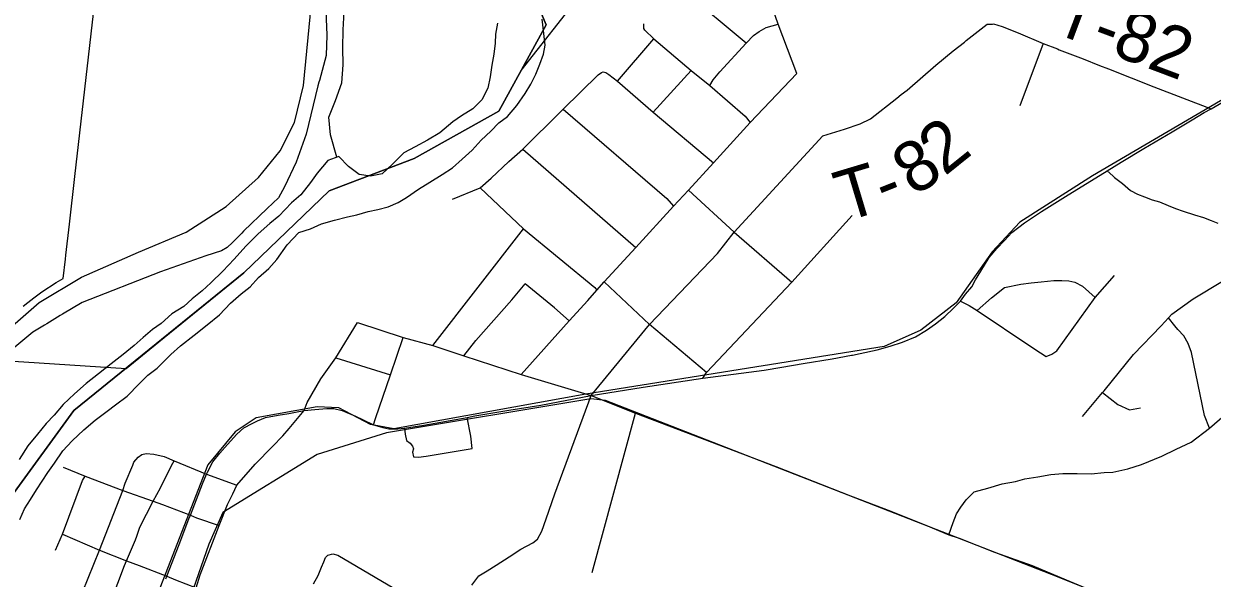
# Model space of a CAD drawing. Extents: x 0 to 34, y 0 to 22.
# Drawn here: x 6.15 to 6.817, y 19.244 to 19.556 of the extents above; entities that cross this region are included whole.
import ezdxf

# ---------------------------------------------------------------- set-up
doc = ezdxf.new("R2010")
doc.units = 0
for name, color, linetype in [('GM_X_City_Street', 7, 'Continuous'), ('GM_X_Corporation', 7, 'Continuous'), ('GM_X_Major_River', 7, 'Continuous'), ('GM_X_Minor_River', 7, 'Continuous'), ('GM_X_Rail_Line', 7, 'Continuous'), ('GM_X_State_Route', 7, 'Continuous'), ('GM_X_Township_Road', 7, 'Continuous'), ('GM_X_Township_Road_Text', 7, 'Continuous'), ('GM_X_US_Route', 7, 'Continuous'), ('SH_Cut_Line', 7, 'Continuous')]:
    doc.layers.add(name, color=color, linetype=linetype)

msp = doc.modelspace()

# ---------------------------------------------------------------- linework, layer by layer
at = {"layer": 'GM_X_City_Street'}
for p, q in [((6.50334, 19.50641), (6.52454, 19.52967)), ((6.43003, 19.48546), (6.49347, 19.43035)), ((6.37953, 19.37514), (6.43036, 19.4408)), ((6.325, 19.36823), (6.35575, 19.35867)), ((6.46904, 19.24777), (6.49342, 19.33712))]:
    msp.add_line(p, q, dxfattribs=at)
for points in [[(6.58393, 19.52802), (6.57342, 19.55579), (6.55805, 19.60066)], [(6.5555, 19.54512), (6.52085, 19.57407), (6.50425, 19.5887)], [(6.14936, 19.39732), (6.15185, 19.3993), (6.15538, 19.40194), (6.15986, 19.40528), (6.16779, 19.41068), (6.17183, 19.4129), (6.17307, 19.42376), (6.17332, 19.42591), (6.17532, 19.44339), (6.17838, 19.47021), (6.1896, 19.56824)], [(6.39057, 19.45735), (6.40608, 19.46378), (6.41225, 19.46922), (6.42214, 19.47865), (6.43003, 19.48546), (6.45143, 19.5067), (6.45277, 19.50808), (6.47232, 19.52724), (6.47433, 19.52865), (6.47522, 19.52897), (6.47676, 19.52869), (6.47844, 19.52748), (6.48324, 19.52383), (6.50371, 19.54758), (6.4985, 19.55238), (6.49811, 19.55341), (6.49811, 19.55474), (6.49811, 19.55603)], [(6.53514, 19.5213), (6.53694, 19.52458), (6.54077, 19.52903), (6.5555, 19.54512), (6.55962, 19.54936), (6.56291, 19.55156), (6.56683, 19.55391), (6.57342, 19.55579)], [(6.50371, 19.54758), (6.52454, 19.52967), (6.53514, 19.5213), (6.55501, 19.50416), (6.55785, 19.50051)], [(6.75399, 19.53263), (6.75918, 19.53061), (6.78456, 19.52061), (6.81685, 19.5082)], [(6.42902, 19.35895), (6.45616, 19.38906), (6.46663, 19.40045), (6.47153, 19.40639), (6.47569, 19.41092), (6.49347, 19.43035), (6.51468, 19.45357), (6.52309, 19.46255), (6.53716, 19.47777), (6.55785, 19.50051), (6.58393, 19.52802)], [(6.48324, 19.52383), (6.50334, 19.50641), (6.53716, 19.47777)], [(6.45277, 19.50808), (6.51096, 19.45779), (6.51468, 19.45357)], [(6.46839, 19.34706), (6.50115, 19.38708), (6.53938, 19.42689), (6.54878, 19.43886), (6.59852, 19.49304)], [(6.7584, 19.47338), (6.76153, 19.47052), (6.7625, 19.46957), (6.76702, 19.46627), (6.7715, 19.46223), (6.77535, 19.46021), (6.77941, 19.45883), (6.78363, 19.4571), (6.78772, 19.45587), (6.79257, 19.45391), (6.79671, 19.45225), (6.80109, 19.45079), (6.80747, 19.4487), (6.81251, 19.44705), (6.81673, 19.44547), (6.82052, 19.44391)], [(6.40608, 19.46378), (6.43036, 19.4408), (6.47053, 19.40789), (6.47153, 19.40639)], [(6.52309, 19.46255), (6.54878, 19.43886), (6.58111, 19.41083)], [(6.53111, 19.35689), (6.53319, 19.36002), (6.58111, 19.41083), (6.61515, 19.44833)], [(6.74455, 19.33541), (6.7558, 19.34885), (6.7566, 19.3498), (6.77313, 19.37018), (6.78863, 19.38622), (6.7928, 19.39075), (6.79464, 19.39275), (6.80676, 19.40143), (6.82307, 19.41137), (6.83765, 19.41924), (6.84065, 19.42155)], [(6.67601, 19.40016), (6.68091, 19.39771), (6.6853, 19.39495), (6.71541, 19.37463), (6.72093, 19.37114), (6.72406, 19.36911), (6.72731, 19.37034), (6.73013, 19.3723), (6.75163, 19.40214), (6.76252, 19.4145)], [(6.6853, 19.39495), (6.69342, 19.40197), (6.70074, 19.40772), (6.70977, 19.40965), (6.71572, 19.41045), (6.72124, 19.411), (6.72835, 19.41168), (6.73283, 19.41174), (6.73676, 19.41149), (6.74019, 19.41082), (6.74449, 19.40849), (6.75163, 19.40214)], [(6.39687, 19.36948), (6.40367, 19.37807), (6.42386, 19.40086), (6.43143, 19.40978)], [(6.45616, 19.38906), (6.44792, 19.39635), (6.43143, 19.40978)], [(6.53319, 19.36002), (6.50115, 19.38708), (6.47569, 19.41092)], [(6.22145, 19.17059), (6.23414, 19.20391), (6.24658, 19.23898), (6.24876, 19.24643), (6.25934, 19.27411), (6.2642, 19.28587), (6.26711, 19.29184), (6.26938, 19.29678), (6.2796, 19.30852), (6.28947, 19.3184), (6.29529, 19.32455), (6.2988, 19.32855), (6.30715, 19.33867), (6.30894, 19.34312), (6.31659, 19.35656), (6.325, 19.36823), (6.33723, 19.38822)], [(6.33723, 19.38822), (6.3628, 19.37967), (6.37953, 19.37514), (6.39687, 19.36948), (6.42902, 19.35895), (6.46839, 19.34706)], [(6.81589, 19.32886), (6.81295, 19.33592), (6.80574, 19.37132), (6.80388, 19.3763), (6.80135, 19.38068), (6.79806, 19.38413), (6.7964, 19.38625), (6.7928, 19.39075)], [(6.34613, 19.33073), (6.34733, 19.33413), (6.35575, 19.35867), (6.3628, 19.37967)], [(6.40145, 19.24049), (6.40535, 19.24585), (6.40992, 19.24856), (6.4151, 19.25188), (6.4224, 19.25649), (6.42893, 19.26073), (6.43575, 19.26426), (6.4382, 19.26644), (6.44073, 19.27098), (6.4431, 19.27778), (6.448, 19.29185), (6.46839, 19.34706)], [(6.7558, 19.34885), (6.76438, 19.34216), (6.77092, 19.33904), (6.77707, 19.34028)], [(6.40163, 19.31733), (6.40077, 19.32423), (6.39883, 19.33486)], [(6.66937, 19.26885), (6.67187, 19.27582), (6.67376, 19.28056), (6.6761, 19.28437), (6.67917, 19.28856), (6.6836, 19.29299), (6.69122, 19.29505), (6.69935, 19.29741), (6.70687, 19.29876), (6.71216, 19.30039), (6.71948, 19.30147), (6.72667, 19.30283), (6.73345, 19.30337), (6.74159, 19.30324), (6.74945, 19.3031), (6.75664, 19.30378), (6.76152, 19.30405), (6.76992, 19.30595), (6.77765, 19.30839), (6.78904, 19.31313), (6.79718, 19.31693), (6.80558, 19.321), (6.81589, 19.32886), (6.82565, 19.33727)], [(6.36347, 19.32871), (6.3639, 19.32533), (6.36477, 19.32188), (6.36673, 19.32031), (6.36798, 19.31874), (6.36853, 19.31709), (6.36806, 19.31529), (6.36853, 19.3127), (6.37151, 19.31239), (6.37575, 19.31309), (6.40163, 19.31733)], [(6.17305, 19.21308), (6.19223, 19.26023), (6.20529, 19.29377), (6.20662, 19.29779), (6.21094, 19.30792), (6.21149, 19.30972), (6.21391, 19.31248)], [(6.21391, 19.31248), (6.21593, 19.31392), (6.21844, 19.31461), (6.22279, 19.31413), (6.22844, 19.31284), (6.23418, 19.31034), (6.25238, 19.30301), (6.26938, 19.29678)], [(6.17186, 19.30693), (6.1841, 19.30173), (6.20529, 19.29377), (6.2224, 19.28784), (6.22753, 19.28594), (6.24325, 19.27994), (6.24662, 19.27837), (6.25934, 19.27411)], [(6.21308, 19.26801), (6.21489, 19.27321), (6.2224, 19.28784), (6.22648, 19.29522), (6.23273, 19.30785), (6.23418, 19.31034)], [(6.16741, 19.26014), (6.17133, 19.26924), (6.18271, 19.29933), (6.1841, 19.30173)], [(6.17133, 19.26924), (6.19223, 19.26023), (6.20737, 19.25427), (6.21446, 19.25154), (6.22998, 19.2456), (6.23483, 19.24351), (6.24658, 19.23898)], [(6.17209, 19.18241), (6.17992, 19.19003), (6.18322, 19.19377), (6.18614, 19.19732), (6.19418, 19.21939), (6.19447, 19.22034), (6.20628, 19.25152), (6.20737, 19.25427), (6.2124, 19.26606), (6.21308, 19.26801)], [(6.31245, 19.24135), (6.31499, 19.24605), (6.31691, 19.25074), (6.31818, 19.25365), (6.31926, 19.2561), (6.32057, 19.25737), (6.32335, 19.25826), (6.32602, 19.25748), (6.34712, 19.24501), (6.3734, 19.22955)]]:
    msp.add_lwpolyline(points, dxfattribs=at)
at = {"layer": 'GM_X_Corporation'}
for points in [[(6.42294, 19.60331), (6.4431, 19.55544), (6.41649, 19.5068), (6.36896, 19.4802), (6.32124, 19.46215), (6.27334, 19.41597), (6.17772, 19.33863), (6.14274, 19.29055)], [(6.14274, 19.29055), (6.17772, 19.33863), (6.27334, 19.41597), (6.32124, 19.46215), (6.36896, 19.4802), (6.41649, 19.5068), (6.4431, 19.55544), (6.42294, 19.60331)], [(6.13514, 19.36702), (6.2071, 19.36229), (6.22562, 19.37721), (6.27334, 19.41597), (6.32124, 19.46215), (6.36896, 19.4802), (6.41649, 19.5068), (6.42905, 19.52976), (6.46297, 19.57308)]]:
    msp.add_lwpolyline(points, dxfattribs=at)
at = {"layer": 'GM_X_Major_River'}
for points in [[(6.26571, 19.39896), (6.27171, 19.40416), (6.27692, 19.40824), (6.28159, 19.41347), (6.2874, 19.41848), (6.29187, 19.42352), (6.29756, 19.43177), (6.30416, 19.43867), (6.31066, 19.44081), (6.31698, 19.44354), (6.32424, 19.44567), (6.33149, 19.44742), (6.33683, 19.44864), (6.34314, 19.4506), (6.34848, 19.45163), (6.3544, 19.45322), (6.35995, 19.45558), (6.36476, 19.45833), (6.37151, 19.46314), (6.37785, 19.467), (6.38478, 19.47123), (6.39056, 19.4751), (6.39598, 19.47993), (6.40159, 19.48495), (6.40665, 19.49055), (6.41207, 19.49557), (6.41654, 19.50042), (6.42136, 19.50393), (6.42662, 19.5101), (6.43132, 19.51685), (6.43448, 19.5221), (6.43726, 19.52775), (6.43965, 19.53321), (6.44167, 19.53887), (6.44254, 19.54399), (6.44193, 19.55047), (6.44096, 19.55866)], [(6.41586, 19.55632), (6.41477, 19.55007)], [(6.41477, 19.55007), (6.41448, 19.54514), (6.41377, 19.53888), (6.41269, 19.53282), (6.4116, 19.52619), (6.41032, 19.51975), (6.40695, 19.51316), (6.4019, 19.50814), (6.39556, 19.50427), (6.39074, 19.50095), (6.38339, 19.49464), (6.37647, 19.4906), (6.36955, 19.48675), (6.36322, 19.48346), (6.35682, 19.47713), (6.351, 19.47173), (6.34452, 19.47034), (6.33809, 19.47124), (6.33211, 19.47573), (6.32673, 19.48136), (6.32042, 19.47921)], [(6.32042, 19.47921), (6.31457, 19.4721), (6.31066, 19.46686), (6.30538, 19.45993), (6.30016, 19.45529), (6.29297, 19.44783), (6.28795, 19.44375), (6.28137, 19.43799), (6.27439, 19.4311), (6.26777, 19.42364), (6.26155, 19.41692), (6.25476, 19.4104), (6.24992, 19.40594), (6.24432, 19.40149), (6.23948, 19.39722), (6.23275, 19.39299), (6.22693, 19.38759), (6.22193, 19.38427), (6.2167, 19.37963), (6.21167, 19.37517), (6.20549, 19.37016), (6.19873, 19.36498), (6.19158, 19.35923), (6.18463, 19.35386), (6.17805, 19.3481), (6.17185, 19.34215), (6.16678, 19.33617), (6.16231, 19.33132), (6.15744, 19.32533), (6.15198, 19.31879), (6.14707, 19.3111)], [(6.14747, 19.27744), (6.15007, 19.28347), (6.15341, 19.28872), (6.15676, 19.29417), (6.1599, 19.29904), (6.16323, 19.30392), (6.16696, 19.30917), (6.17166, 19.3161), (6.17691, 19.3217), (6.18331, 19.32784), (6.18969, 19.33322), (6.19644, 19.33841), (6.20127, 19.34192), (6.20782, 19.34673), (6.21443, 19.35363), (6.21928, 19.35847), (6.22468, 19.36254), (6.23225, 19.37018), (6.23767, 19.37502), (6.24539, 19.38094), (6.25273, 19.38687), (6.25969, 19.39243), (6.26571, 19.39896)]]:
    msp.add_lwpolyline(points, dxfattribs=at)
at = {"layer": 'GM_X_Minor_River'}
msp.add_lwpolyline([(6.32554, 19.48095), (6.32192, 19.49355), (6.32096, 19.50344), (6.32477, 19.51295), (6.32839, 19.52284), (6.32915, 19.53292), (6.32896, 19.54243), (6.32915, 19.55251), (6.32972, 19.56278)], dxfattribs=at)
at = {"layer": 'GM_X_Rail_Line'}
for points in [[(6.14038, 19.38358), (6.15835, 19.39942), (6.18212, 19.41364), (6.21405, 19.42773), (6.24096, 19.43885), (6.26335, 19.45328), (6.28157, 19.46968), (6.29361, 19.48468), (6.30179, 19.50058), (6.30675, 19.52121), (6.33234, 19.78369)], [(7.16666, 19.69799), (6.88858, 19.5517), (6.75005, 19.47049), (6.70933, 19.44446), (6.69366, 19.42791), (6.67358, 19.39914), (6.65363, 19.38387), (6.63306, 19.37462), (6.46537, 19.34794), (6.35756, 19.32849), (6.3445, 19.33077), (6.32664, 19.34017), (6.31455, 19.34079), (6.28029, 19.33452), (6.2685, 19.3267), (6.25312, 19.30824), (6.20517, 19.18488), (6.19916, 19.18173), (6.18438, 19.18787), (6.15614, 19.1781)], [(6.82933, 19.19058), (6.80388, 19.21062), (6.77117, 19.22902), (6.73048, 19.24516), (6.47648, 19.34433), (6.46819, 19.34526), (6.35348, 19.32621), (6.31452, 19.3139), (6.26142, 19.28137), (6.25364, 19.26353), (6.24478, 19.23826), (6.21672, 19.16563), (6.20176, 19.13911), (6.18685, 19.12272), (6.17394, 19.11168)]]:
    msp.add_lwpolyline(points, dxfattribs=at)
at = {"layer": 'GM_X_State_Route'}
for points in [[(6.35145, 19.78351), (6.34339, 19.77343), (6.3352, 19.76468), (6.32755, 19.6906), (6.32589, 19.6746), (6.31951, 19.59047), (6.31938, 19.56328), (6.31988, 19.54957), (6.31955, 19.53818), (6.31576, 19.5241)], [(6.31576, 19.5241), (6.31549, 19.52309), (6.31495, 19.52108), (6.30838, 19.49401), (6.30272, 19.47829), (6.29619, 19.46433), (6.29267, 19.45822), (6.28633, 19.45224), (6.27319, 19.43938)], [(6.68442, 19.41203), (6.68733, 19.41704), (6.69204, 19.42473), (6.69639, 19.42981), (6.70068, 19.43424), (6.70472, 19.43874), (6.71188, 19.44407), (6.72153, 19.45046), (6.73638, 19.45995), (6.74951, 19.4679), (6.7584, 19.47338), (6.76629, 19.47821), (6.77896, 19.48588), (6.79491, 19.49526), (6.8061, 19.50195), (6.8129, 19.50606), (6.81685, 19.5082), (6.82348, 19.5122)], [(6.27319, 19.43938), (6.27209, 19.43831), (6.26684, 19.43318), (6.26387, 19.43027), (6.26074, 19.42833), (6.25189, 19.42569), (6.22642, 19.41661), (6.18236, 19.39945), (6.17136, 19.39279)], [(6.61474, 19.36973), (6.61522, 19.36982), (6.61967, 19.37067), (6.62921, 19.3727), (6.63647, 19.37479), (6.64336, 19.37708), (6.65065, 19.38012), (6.65681, 19.38376), (6.66184, 19.38743), (6.66719, 19.39146), (6.67193, 19.39623), (6.67601, 19.40016), (6.67873, 19.40402), (6.68225, 19.40826), (6.68442, 19.41203)], [(6.17136, 19.39279), (6.17004, 19.39199), (6.16256, 19.38747)], [(6.16256, 19.38747), (6.16124, 19.38667), (6.15464, 19.38267), (6.13412, 19.36575), (6.12231, 19.34842), (6.11584, 19.33511)], [(6.57552, 19.36307), (6.58747, 19.36504), (6.60385, 19.36766), (6.61474, 19.36973)], [(6.53111, 19.35689), (6.56556, 19.36143), (6.57552, 19.36307)], [(6.46839, 19.34706), (6.49758, 19.3519), (6.53111, 19.35689)]]:
    msp.add_lwpolyline(points, dxfattribs=at)
at = {"layer": 'GM_X_Township_Road'}
msp.add_line((6.72238, 19.54498), (6.70928, 19.50983), dxfattribs=at)
for points in [[(6.64268, 19.51617), (6.6459, 19.51877), (6.66204, 19.53279), (6.67192, 19.54073), (6.67813, 19.54572), (6.6791, 19.5465), (6.68589, 19.55184), (6.69093, 19.55583), (6.69349, 19.55585), (6.69401, 19.55585)], [(6.69401, 19.55585), (6.69452, 19.55586), (6.69931, 19.55453), (6.70826, 19.55083)], [(6.70826, 19.55083), (6.72238, 19.54498), (6.73041, 19.54182), (6.7314, 19.54143)], [(6.7314, 19.54143), (6.73289, 19.54085), (6.74481, 19.53621), (6.75399, 19.53263)], [(6.59852, 19.49304), (6.61076, 19.4968), (6.61958, 19.49968), (6.62535, 19.50261), (6.64026, 19.51422), (6.64268, 19.51617)]]:
    msp.add_lwpolyline(points, dxfattribs=at)
at = {"layer": 'GM_X_US_Route'}
for points in [[(6.30236, 19.33776), (6.30715, 19.33867), (6.31315, 19.33931), (6.31991, 19.33987), (6.32378, 19.33987), (6.32861, 19.33868), (6.33595, 19.33544), (6.33993, 19.33362), (6.34613, 19.33073), (6.35137, 19.32918), (6.35484, 19.32847), (6.35973, 19.32847), (6.36347, 19.32871), (6.3744, 19.33052), (6.39883, 19.33486), (6.40305, 19.33561), (6.42226, 19.33882), (6.44024, 19.34168), (6.46839, 19.34706)], [(6.46839, 19.34706), (6.49342, 19.33712), (6.57226, 19.30715), (6.61419, 19.29076), (6.63682, 19.28218), (6.65653, 19.27428), (6.66937, 19.26885)], [(6.22942, 19.24416), (6.22998, 19.2456), (6.23694, 19.26334), (6.24245, 19.27783), (6.24325, 19.27994), (6.24998, 19.29758), (6.25238, 19.30301), (6.2528, 19.30396), (6.2558, 19.30978), (6.25973, 19.3148), (6.26417, 19.31957), (6.26928, 19.32534), (6.27337, 19.32889), (6.27799, 19.33142), (6.2809, 19.33293), (6.2855, 19.3347), (6.2925, 19.33606), (6.29853, 19.33703), (6.30236, 19.33776)], [(6.66937, 19.26885), (6.67524, 19.2669), (6.69505, 19.25915), (6.71621, 19.25152), (6.73762, 19.24266), (6.74882, 19.23799), (6.76075, 19.23368), (6.76374, 19.23236)]]:
    msp.add_lwpolyline(points, dxfattribs=at)
at = {"layer": 'SH_Cut_Line'}
for points in [[(6.14274, 19.29055), (6.17772, 19.33863), (6.27334, 19.41597), (6.32124, 19.46215), (6.36896, 19.4802), (6.41649, 19.5068), (6.4431, 19.55544), (6.42294, 19.60331)], [(6.42294, 19.60331), (6.4431, 19.55544), (6.41649, 19.5068), (6.36896, 19.4802), (6.32124, 19.46215), (6.27334, 19.41597), (6.17772, 19.33863), (6.14274, 19.29055)]]:
    msp.add_lwpolyline(points, dxfattribs=at)

# ---------------------------------------------------------------- texts
at = {"layer": 'GM_X_Township_Road_Text'}
for s, height, rotation, p in [('T-82', 0.028409, 339.38696, (6.72655, 19.55154)), ('2', 0.02841, 38.75218, (6.66702, 19.47005)), ('8', 0.02841, 33.06132, (6.64987, 19.4587)), ('T', 0.02841, 16.72716, (6.61069, 19.44456)), ('-', 0.02841, 21.74961, (6.63361, 19.45157))]:
    msp.add_text(s, height=height, rotation=rotation, dxfattribs=at).set_placement(p)

doc.saveas('drawing.dxf')
